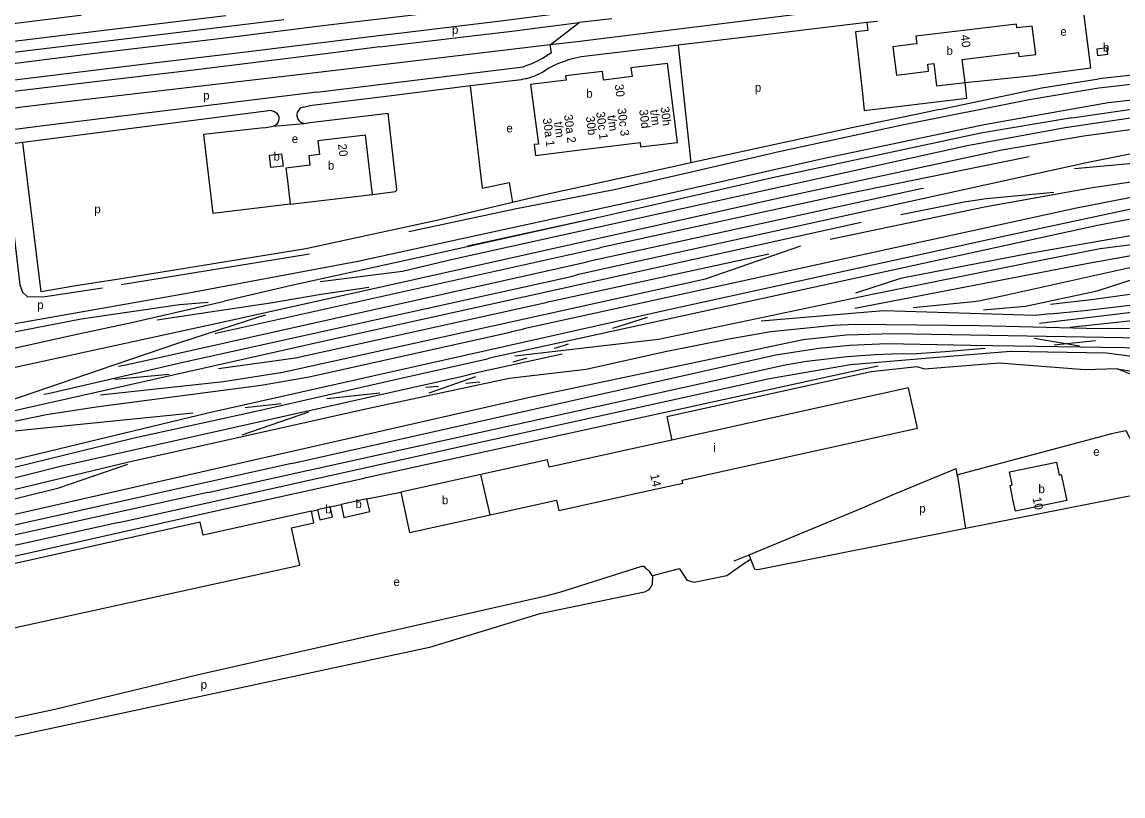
# Model space of a CAD drawing. Extents: x 161494 to 163033, y 383688 to 384862.
# Drawn here: x 162005 to 162517, y 383712 to 384073 of the extents above; entities that cross this region are included whole.
import ezdxf

# ---------------------------------------------------------------- set-up
doc = ezdxf.new("R2010")
doc.units = 0
for name, color, linetype in [('BLT_Basislijn', 7, 'Continuous'), ('BLT_Bebouwing', 7, 'Continuous'), ('BLT_Centroide', 7, 'Continuous'), ('BLT_Huisnummer', 7, 'Continuous'), ('BLT_Huisnummer_reeks', 7, 'Continuous'), ('BLT_Onderverdeling_panden', 7, 'Continuous'), ('BLT_Spoorlijn', 7, 'Continuous'), ('BLT_Vlakafsluiter', 7, 'Continuous')]:
    doc.layers.add(name, color=color, linetype=linetype)

msp = doc.modelspace()

# ---------------------------------------------------------------- linework, layer by layer
at = {"layer": 'BLT_Basislijn'}
for p, q in [((162126.86, 384073.58), (162015.41, 384059.99)), ((162099.94, 384075.38), (162038.28, 384067.96)), ((162402.95, 384072.84), (162397.98, 384072.25)), ((162397.98, 384072.25), (162398.41, 384068.65)), ((162038.28, 384067.96), (162016.53, 384065.35)), ((162016.53, 384065.35), (161970.53, 384059.79)), ((162250.72, 384061.85), (162144.18, 384049.27)), ((162263.36, 384063.34), (162250.72, 384061.85)), ((162251.31, 384058.43), (162250.72, 384061.85)), ((162310.31, 384061.73), (162304.32, 384061.01)), ((162310.31, 384061.73), (162316.22, 384006.99)), ((162015.41, 384059.99), (161924.88, 384049.24)), ((162304.32, 384061.01), (162265.1, 384056.31)), ((162142.18, 384039.89), (162238.14, 384051.73)), ((162144.18, 384049.27), (162016.75, 384034.31)), ((162443.66, 384044.4), (162473.95, 384047.55)), ((162551.62, 384051.16), (162505.86, 384046.13)), ((162213.64, 384042.77), (162174.52, 384037.93)), ((162237.25, 384045.7), (162213.64, 384042.77)), ((162219.25, 383995.24), (162213.64, 384042.77)), ((162142.18, 384039.89), (162017.64, 384024.49)), ((162174.52, 384037.93), (162138.87, 384033.51)), ((162016.75, 384034.31), (161960.62, 384027.39)), ((162120.98, 384031.33), (162088.58, 384027.16)), ((162135.87, 384032.98), (162138.87, 384033.51)), ((162088.58, 384027.16), (162005.59, 384016.47)), ((162136.37, 384025.38), (162138.97, 384025.83)), ((162138.97, 384025.83), (162141.65, 384026.15)), ((162141.65, 384026.15), (162175.35, 384030.07)), ((162117.62, 384023.23), (162089.48, 384020.18)), ((162117.62, 384023.23), (162122.09, 384024.04)), ((162122.09, 384024.04), (162136.37, 384025.38)), ((162005.59, 384016.47), (161998.45, 384015.55)), ((162089.48, 384020.18), (162093.89, 383983.46)), ((162311.36, 384005.93), (162246.2, 383991.7)), ((162316.22, 384006.99), (162311.36, 384005.93)), ((162246.2, 383991.7), (162233.2, 383988.6)), ((162129.89, 383987.73), (162093.89, 383983.46)), ((162051.28, 383950.46), (162138.8, 383964.68)), ((162411.05, 383853), (162439.57, 383864.71)), ((162440.16, 383861.18), (162439.57, 383864.71)), ((162165.51, 383850.67), (162181.24, 383853.7)), ((162148.51, 383846.88), (162153.51, 383847.98)), ((162139.81, 383844.85), (162142.61, 383845.56)), ((162344.15, 383822.1), (162343.24, 383824.58))]:
    msp.add_line(p, q, dxfattribs=at)
for points in [[(162037.04, 384088.82), (162036.53, 384080.07), (162035.9, 384078.31), (162034.83, 384076.99), (162033.62, 384076.14), (162032.14, 384075.62), (161973.45, 384068.36), (161971.82, 384068.3), (161970.32, 384068.57), (161968.94, 384069.14), (161967.71, 384069.97), (161966.53, 384071.23), (161965.71, 384072.68), (161965.29, 384073.99), (161965.13, 384075.37), (161965.09, 384077.77), (161965.12, 384080.52)], [(162474.93, 384090.36), (162374.06, 384077.18), (162263.36, 384063.34)], [(162473.95, 384047.55), (162502.09, 384051.2), (162498.03, 384084.42)], [(162212.3, 384078.63), (162147.57, 384071.14), (162099.53, 384065.02), (162042.92, 384058.28)], [(162257.94, 384076.77), (162229.07, 384073.11), (162180.34, 384067.19), (162170.91, 384066.06)], [(162171.47, 384060.99), (162213.02, 384065.92), (162231.75, 384068.17), (162264.28, 384072.26)], [(162279.49, 384074.03), (162264.28, 384072.26)], [(162397.98, 384072.25), (162341.73, 384065.49), (162310.31, 384061.73)], [(162398.41, 384068.65), (162392.66, 384067.99), (162395.96, 384039.21), (162396.82, 384031.44), (162444.53, 384037.15), (162443.66, 384044.4)], [(162170.91, 384066.06), (162109.23, 384058.59), (162065, 384053.23)], [(162042.92, 384058.28), (161985.85, 384051.24), (161928.63, 384044.5)], [(162171.47, 384060.99), (162144.99, 384057.6), (162116.12, 384053.94), (162085, 384050.13), (162065.15, 384047.88)], [(162238.14, 384051.73), (162240.01, 384052.39), (162241.85, 384053.12), (162243.66, 384053.93), (162245.43, 384054.81), (162247.17, 384055.76), (162248.86, 384056.78), (162250.52, 384057.87), (162251.31, 384058.43)], [(162065, 384053.23), (161972.34, 384041.96), (161944.6, 384038.44)], [(162184.97, 383975.01), (162234.27, 383985.59), (162280.45, 383994.61), (162317.07, 384003.01), (162357.89, 384012.37), (162415.17, 384024.78), (162473.52, 384036.49), (162505.94, 384041.95), (162556.37, 384047.61), (162586.74, 384050.32), (162625.03, 384052.18), (162657.62, 384052.19), (162690.5, 384051.66)], [(162265.1, 384056.31), (162263.12, 384055.91), (162261.15, 384055.43), (162259.2, 384054.87), (162257.28, 384054.23), (162255.38, 384053.52), (162253.51, 384052.73), (162251.68, 384051.88), (162249.79, 384050.9)], [(162065.15, 384047.88), (162001.35, 384040.13), (161948.68, 384033.93)], [(162239.64, 384046.15), (162239.17, 384046.04), (162237.72, 384045.77), (162237.25, 384045.7)], [(162249.79, 384050.9), (162248.6, 384050.04), (162247.35, 384049.26), (162246.07, 384048.54), (162244.75, 384047.89), (162243.39, 384047.31), (162242.01, 384046.81), (162240.6, 384046.39), (162239.64, 384046.15)], [(162431.72, 384031.85), (162479.43, 384041.97), (162505.86, 384046.13)], [(162956.78, 384021.72), (162940.81, 384022.86), (162844.13, 384032.25), (162776, 384038.39), (162705.31, 384043.59), (162655, 384044.9), (162627.45, 384044.8), (162579.26, 384042.49), (162510.26, 384034.87), (162452.51, 384024.7), (162377.46, 384008.85), (162301.58, 383991.65), (162233.15, 383976.81), (162161.35, 383961.08), (162082.65, 383946.35), (162000.1, 383931.74), (161945.86, 383921.22), (161938.95, 383921.37)], [(162120.98, 384031.33), (162121.52, 384031.27), (162122.06, 384031.12), (162122.56, 384030.91), (162123.02, 384030.62), (162123.44, 384030.26), (162123.81, 384029.85), (162124.11, 384029.4), (162124.34, 384028.9), (162124.49, 384028.37), (162124.57, 384027.83), (162124.57, 384027.28), (162124.48, 384026.74), (162124.32, 384026.22), (162124.09, 384025.72), (162123.78, 384025.27), (162123.42, 384024.86), (162122.99, 384024.51), (162122.52, 384024.23), (162122.09, 384024.04)], [(162135.87, 384032.98), (162135.34, 384032.8), (162134.84, 384032.55), (162134.39, 384032.23), (162133.98, 384031.85), (162133.64, 384031.42), (162133.35, 384030.93), (162133.15, 384030.42), (162133.01, 384029.88), (162132.96, 384029.32), (162132.99, 384028.77), (162133.09, 384028.22), (162133.27, 384027.7), (162133.53, 384027.2), (162133.85, 384026.75), (162134.24, 384026.35), (162134.68, 384026.01), (162135.16, 384025.73), (162135.68, 384025.53), (162136.22, 384025.4), (162136.37, 384025.38)], [(162431.72, 384031.85), (162423.85, 384030.18), (162391.05, 384023.32), (162316.22, 384006.99)], [(162168.17, 383992.34), (162178.74, 383993.7), (162179.33, 383994.07), (162179.41, 383994.62), (162175.35, 384030.07)], [(162017.64, 384024.49), (161979.82, 384019.8), (161964.19, 384023.37)], [(162233.2, 383988.6), (162198.65, 383980.36), (162137.19, 383967.01), (162051.32, 383953.01), (162029.31, 383949.67), (162013.98, 383947), (162005.59, 384016.47)], [(161997.08, 384010.02), (162004.14, 383950.22), (162005.39, 383946.88), (162007.62, 383944.64), (162015.93, 383944.83), (162042.51, 383948.79)], [(162219.25, 383995.24), (162231.67, 383997.8), (162233.2, 383988.6)], [(162514.37, 383911.16), (162573.7, 383901.56), (162613.61, 383900.68), (162655.85, 383904.66), (162788.99, 383916.53), (162852.19, 383929.33), (162857.95, 383930.73)], [(162459.47, 383913.71), (162424.85, 383911.06), (162421.45, 383912.07), (162400.03, 383909.78), (162304.94, 383888.77), (162307.31, 383878.02)], [(162514.37, 383911.16), (162499.43, 383910.67), (162459.47, 383913.71)], [(162524.19, 383906.26), (162521.33, 383908.32), (162514.37, 383911.16)], [(162524.4, 383869.94), (162523.12, 383873.79), (162518.74, 383881.94), (162518.35, 383882.35), (162511.81, 383880.82), (162440.37, 383861.85), (162440.16, 383861.18)], [(162440.16, 383861.18), (162443.86, 383836.78)], [(162527.6, 383858.28), (162527.82, 383857.32), (162527.69, 383855.14), (162526.15, 383853.19), (162524.72, 383852.77), (162443.86, 383836.78)], [(162343.24, 383824.58), (162395.99, 383846.52), (162411.05, 383853)], [(162443.86, 383836.78), (162347.36, 383817.56), (162345.99, 383817.74), (162344.15, 383822.1)], [(162344.15, 383822.1), (162343.67, 383822.22), (162340.77, 383820.4), (162332.94, 383814.78), (162317.73, 383811.68), (162314.64, 383812.66), (162311.04, 383818.01), (162310.18, 383817.93), (162298.39, 383814.86)], [(162336.35, 383821.72), (162343.24, 383824.58)], [(161857.05, 383717.49), (161900, 383726.97), (162020.37, 383752.79), (162087.25, 383768.84), (162248.7, 383805.52), (162255.21, 383807.22), (162293.41, 383819.32), (162294.37, 383819.23), (162295.04, 383818.42), (162296.07, 383817.77)], [(162298.39, 383814.86), (162297.95, 383815.15), (162297.13, 383816.68), (162296.07, 383817.77)], [(162298.39, 383814.86), (162298.2, 383810.83), (162297.43, 383809.38), (162296.37, 383808.09), (162294.68, 383807.19), (162245.95, 383797.11), (162194.64, 383781.44), (161900, 383718.26), (161896.94, 383717.62), (161877.03, 383714.47), (161850.45, 383712.34)]]:
    msp.add_lwpolyline(points, dxfattribs=at)
at = {"layer": 'BLT_Bebouwing'}
for p, q in [((162467.57, 384071.6), (162425.99, 384066.57)), ((162425.99, 384066.57), (162420.75, 384065.93)), ((162476.27, 384057.43), (162476.52, 384057.46)), ((162309.88, 384016.49), (162305.31, 384053.28)), ((162129.89, 383987.73), (162168.17, 383992.34)), ((162362.65, 383890.25), (162307.31, 383878.02)), ((162307.31, 383878.02), (162288.81, 383873.93)), ((162288.81, 383873.93), (162250.29, 383865.43)), ((162218.56, 383861.94), (162181.24, 383853.7)), ((162222.78, 383843.26), (162253.68, 383850.09))]:
    msp.add_line(p, q, dxfattribs=at)
for points in [[(162474.92, 384070.68), (162467.78, 384069.81), (162467.57, 384071.6)], [(162476.52, 384057.46), (162474.92, 384070.68)], [(162419.66, 384062.17), (162410.12, 384061.01), (162411.72, 384047.8), (162426.73, 384049.61), (162426.33, 384052.96), (162429.18, 384053.3), (162430.46, 384042.8)], [(162420.75, 384065.93), (162421.18, 384062.35), (162419.66, 384062.17)], [(162430.46, 384042.8), (162443.66, 384044.4), (162442.36, 384055.14), (162468.46, 384058.3), (162468.68, 384056.51), (162472.78, 384057.01)], [(162472.78, 384057.01), (162476.52, 384057.46)], [(162305.31, 384053.28), (162288.3, 384051.19), (162288.8, 384047.12), (162275.51, 384045.49), (162275.01, 384049.56), (162257.93, 384047.45), (162258.16, 384045.55), (162241.64, 384043.39), (162245.26, 384015.73), (162243.3, 384015.48), (162243.91, 384010.46), (162262.15, 384012.81), (162292.53, 384016.51), (162292.78, 384014.41), (162309.88, 384016.49)], [(162142.71, 384017.26), (162143.47, 384010.93), (162138.45, 384010.33), (162138.98, 384005.87), (162127.85, 384004.53), (162128.4, 384000), (162129.89, 383987.73)], [(162168.17, 383992.34), (162167.25, 384000), (162164.84, 384019.93), (162142.71, 384017.26)], [(162120.2, 384010.53), (162125.88, 384011.21), (162126.56, 384005.53), (162120.89, 384004.85), (162120.2, 384010.53)], [(162366.8, 383871.47), (162421.56, 383883.57), (162417.41, 383902.34), (162362.65, 383890.25)], [(162250.29, 383865.43), (162249.55, 383868.79), (162218.56, 383861.94)], [(162293.27, 383853.7), (162312.37, 383857.91), (162312.05, 383859.38), (162366.8, 383871.47)], [(162181.24, 383853.7), (162185.38, 383835), (162222.78, 383843.26)], [(162253.68, 383850.09), (162254.76, 383845.19), (162293.27, 383853.7)], [(162142.61, 383845.56), (162143.66, 383840.86), (162149.56, 383842.19), (162148.51, 383846.88)], [(162148.51, 383846.88), (162142.61, 383845.56)], [(162153.51, 383847.98), (162154.85, 383841.99), (162166.85, 383844.68), (162165.51, 383850.67)], [(162165.51, 383850.67), (162153.51, 383847.98)], [(162000, 383790.34), (162134.33, 383819.8), (162130.48, 383837.21), (162140.9, 383839.53), (162139.81, 383844.85)], [(162139.81, 383844.85), (162089.38, 383833.76), (162088.04, 383839.79), (162000, 383820.13)]]:
    msp.add_lwpolyline(points, dxfattribs=at)
for points in [[(162504.98, 384059.97), (162505.29, 384057.02), (162510.02, 384057.57), (162509.69, 384060.51)], [(162490.96, 383849.84), (162467.12, 383844.83), (162466.11, 383849.64), (162464.61, 383856.9), (162465.6, 383857.11), (162464.33, 383863.19), (162486.15, 383867.78), (162487.44, 383861.7), (162488.43, 383861.91)]]:
    msp.add_lwpolyline(points, close=True, dxfattribs=at)
at = {"layer": 'BLT_Onderverdeling_panden'}
msp.add_line((162222.78, 383843.26), (162218.56, 383861.94), dxfattribs=at)
at = {"layer": 'BLT_Spoorlijn'}
for p, q in [((162483.18, 383936.8), (162476.31, 383935.97)), ((162508.37, 383935.84), (162478.25, 383932.3)), ((162529.41, 383934.28), (162492.32, 383930.4)), ((162475.74, 383925.46), (162496.84, 383921.86)), ((162485.12, 383922.28), (162504.3, 383924.29)), ((162073.54, 383908.58), (162048.26, 383906.16)), ((162192.96, 383902.62), (162198.77, 383903.13)), ((162194.47, 383899.99), (162216.19, 383907.59)), ((162146.86, 383897.28), (162171.6, 383900.03)), ((162108.95, 383893.19), (162125.62, 383895.06)), ((162138.29, 383890.98), (162107.29, 383880.28))]:
    msp.add_line(p, q, dxfattribs=at)
for points in [[(162851.52, 384017.92), (162815.39, 384024.3), (162780.35, 384028.34), (162734.32, 384032.49), (162682.28, 384035.6), (162657.55, 384036.07), (162644.62, 384036.06), (162620.91, 384035.6), (162600, 384034.57), (162572.62, 384033.21), (162544.84, 384030.9), (162520.54, 384027.83), (162490.18, 384023.26), (162444.69, 384014.9), (162206.08, 383962.22), (162182.09, 383956.51), (162143.86, 383951.57)], [(162493.36, 384027.95), (162525.34, 384032.6), (162559.19, 384036.38), (162587.86, 384038.71), (162602.55, 384039.57), (162618.77, 384040.28), (162643.1, 384040.8), (162670.1, 384040.71)], [(162900.86, 384011.36), (162871.5, 384014.34), (162849.2, 384016.61), (162786.11, 384023.02), (162743.32, 384027.37), (162714.49, 384029.62), (162675.59, 384031.05), (162617.43, 384030.81), (162571.29, 384028.11), (162530.64, 384023.81), (162498.89, 384019.36), (162460.78, 384012.83), (162360.78, 383991.35), (162187.34, 383952.61), (162103.09, 383933.78), (162003.41, 383912.03), (161897.47, 383888.44), (161858.44, 383879.75), (161796.71, 383866.01)], [(162015.34, 383899.38), (162017.25, 383899.68), (162080.65, 383914.34), (162260.47, 383954.06), (162264.14, 383955.18), (162275.03, 383957.62), (162500.2, 384007.1), (162541.18, 384015.46), (162562.76, 384019.37), (162588.28, 384023.03), (162600, 384024.15), (162615.59, 384025.65), (162626.19, 384026.21), (162676.14, 384026.61), (162705.93, 384025.41), (162732.39, 384023.5), (162757.2, 384021.52), (162782.07, 384018.89)], [(162493.36, 384027.95), (162450.96, 384020.86), (162354.12, 384000)], [(162718.29, 384020.75), (162713.88, 384020.92), (162695.07, 384020.96), (162676.79, 384020.24), (162656.02, 384019.05), (162600, 384013.9), (162494.64, 384004.23)], [(162941.48, 383999.68), (162885.08, 384004.73), (162828.99, 384008.31), (162785.99, 384009.38), (162740.84, 384009.38), (162711.24, 384008.27), (162666.85, 384005.72), (162629.14, 384002.14), (162592.38, 383997.29), (162554.12, 383991.4), (162521.58, 383985.67), (162460.79, 383972.63), (162306.5, 383938.7), (162091.55, 383890.56), (161917.85, 383848.6), (161738.59, 383808.47)], [(162095.01, 383927.45), (162095.33, 383927.68), (162273.9, 383967.38), (162274.44, 383967.78), (162386.85, 383992.3), (162388.93, 383992.71), (162450.6, 384005.36), (162473.49, 384009.96)], [(162611.49, 384009.61), (162600, 384008.23), (162554.37, 384002.74), (162541.63, 384001.06), (162502.06, 383995.25), (162452.78, 383986.34), (162381.01, 383971.32)], [(162905.58, 383999.21), (162868.86, 384001.46), (162849.7, 384002.66), (162790.91, 384004.97), (162738.08, 384005.04), (162706.63, 384003.77), (162665.91, 384000.87), (162614.64, 383996.13), (162600, 383994.1), (162581.38, 383991.52), (162547.62, 383985.93), (162505.3, 383977.83), (162222.56, 383916.14), (162220.88, 383915.5), (162180.02, 383906.4), (162114.68, 383891.49), (162057.27, 383878.89), (162001, 383865.09), (161973.74, 383858.18), (161900, 383840.1), (161740.55, 383804.02)], [(161730.85, 383826.01), (161894.71, 383863.07), (161900, 383864.57), (161902.38, 383864.96), (161983.42, 383883.13), (162016.6, 383889.91), (162039.67, 383893.48), (162116.35, 383903.49), (162138.72, 383907.4), (162232.76, 383928.3), (162232.82, 383928.45), (162238.5, 383929.73), (162238.57, 383929.89), (162495.51, 383986.06), (162549.61, 383996.68)], [(162050.01, 383912.39), (162052.66, 383912.83), (162073.16, 383917.38), (162267.95, 383960.93), (162268.01, 383961.09), (162423.18, 383995.14), (162424.3, 383995.25)], [(162354.12, 384000), (162272.82, 383981.43)], [(162907.68, 383994.11), (162844.71, 383995.65), (162793.91, 383994.99), (162738.55, 383993.66), (162714.69, 383992.18), (162687.37, 383990.08), (162600, 383981.71), (162536.18, 383975.6), (162528.51, 383974.48), (162472.93, 383964.7), (162413.7, 383953.16), (162392.67, 383946.32)], [(162413.77, 383982.9), (162443.28, 383988.79), (162453.46, 383990.34), (162484.93, 383993.36)], [(162452.21, 383938.56), (162471.82, 383940.35), (162505.05, 383947.43), (162546.3, 383960.72), (162600, 383972.91), (162658.88, 383985.79)], [(162272.82, 383981.43), (162190.66, 383963.17), (162130.51, 383949.89)], [(162272.82, 383981.43), (162212.27, 383968.16)], [(162395.33, 383979.18), (162144.35, 383923.63), (161977.36, 383886.22), (161907.71, 383872.27), (161900, 383871.29), (161780.14, 383857.4), (161723.5, 383844.79)], [(162234.3, 383917.16), (162301.05, 383924.91), (162401.28, 383946), (162480.43, 383961.98), (162506.53, 383967.15), (162525.98, 383969.57), (162555.06, 383972.87), (162619.14, 383978.6)], [(162937.09, 383979.39), (162885.92, 383963.59), (162838.53, 383952.88), (162810.99, 383946.65), (162798.67, 383945.04), (162734.95, 383938.99), (162640.6, 383930.03), (162616.88, 383927.78), (162559, 383928.82), (162530.82, 383929.76), (162500.1, 383929.97)], [(162392.46, 383939.3), (162500.09, 383960.2), (162519.93, 383963.73), (162538.91, 383966.11), (162578.77, 383969.81)], [(162041.67, 383899.09), (162098.83, 383905.26), (162126.37, 383909.55), (162323.01, 383953.08), (162367.37, 383968.42)], [(162096.48, 383911.28), (162132.24, 383916.25), (162249.49, 383942.13), (162249.55, 383942.29), (162251.13, 383942.64), (162352.39, 383964.66)], [(162419.59, 383939.61), (162447.63, 383942.41), (162450.08, 383942.82), (162463.07, 383945.51), (162524.5, 383959.22)], [(162483.42, 383941.17), (162502.43, 383943.42), (162520.33, 383945.85), (162522.52, 383946.03), (162557.82, 383951.09), (162600, 383954.91), (162606.92, 383955.53)], [(162068.05, 383933.95), (162095.81, 383938.09), (162120.73, 383941.8), (162144.3, 383945.84), (162166.42, 383949.19)], [(162130.51, 383949.89), (162099.3, 383942.63)], [(162483.18, 383936.8), (162499.25, 383938.35), (162550.66, 383944.41), (162600, 383948.85), (162607.49, 383949.53)], [(161717.09, 383867.34), (161891.12, 383897), (161932.12, 383905.15), (161966.91, 383913.19), (162031.41, 383927.43), (162056.89, 383932.93), (162099.3, 383942.63)], [(162091.72, 383942.03), (162078.35, 383940.97), (162032.72, 383934.33)], [(162685.4, 383942.61), (162638.15, 383937.9), (162627.72, 383936.86), (162596.57, 383936.35), (162554.47, 383937.41), (162527.37, 383938.1), (162508.37, 383935.84)], [(161973.61, 383887.7), (161975.27, 383888.11), (162047.51, 383912.9), (162078.57, 383923.36), (162115.77, 383935.53), (162118.45, 383936.24)], [(162032.72, 383934.33), (161999.97, 383927.9)], [(162279.85, 383930.06), (162296.05, 383935.21)], [(162476.31, 383935.97), (162405.74, 383938.2), (162348.83, 383933.3)], [(162423.37, 383915.96), (162442.18, 383917.5), (162464.81, 383919.36), (162481.96, 383919.04), (162509.3, 383918.54), (162531.03, 383915.8), (162561.33, 383911.2), (162576.79, 383910.32), (162609.28, 383908.25), (162632.92, 383907.84), (162656.75, 383909.89), (162799.49, 383923.96), (162812.19, 383926.35), (162852.54, 383935.02)], [(162500.1, 383929.97), (162450.25, 383931.18), (162392.65, 383931.81), (162382.47, 383931.26), (162353.39, 383928.39), (162334.69, 383925.09), (162304.14, 383919.1), (162267.53, 383910.9), (162231.75, 383906.69), (162166.47, 383892.65)], [(162584.74, 383924.89), (162561.28, 383924.73), (162410.59, 383927.36), (162388.32, 383926.8), (162368.34, 383924.63), (162241.85, 383897.88), (162061.12, 383856.79)], [(162091.56, 383853.64), (162360.09, 383912.97), (162369.87, 383914.65), (162388.83, 383916.92), (162401.93, 383917.87), (162409.4, 383918.11), (162421.07, 383918.2)], [(162130.47, 383867.03), (162355.7, 383917.69), (162375.71, 383920.79), (162390.03, 383922.19), (162407.33, 383922.9), (162446.26, 383922.2), (162538.25, 383920.77)], [(162252.57, 383920.77), (162253.49, 383920.89), (162259.21, 383922.76)], [(162421.07, 383918.2), (162434.41, 383919.26), (162453.05, 383920.75)], [(162256.39, 383917.91), (162217.24, 383909.43), (162209.3, 383907.49), (162022.98, 383865.7), (161954.74, 383848.51), (161900, 383835.54), (161866.29, 383827.45), (161742.42, 383799.74)], [(162050.18, 383839.64), (162207.72, 383874.76), (162352.68, 383906.66), (162390.4, 383913.21), (162423.37, 383915.96)], [(162233.47, 383914.4), (162240.03, 383916.28)], [(161754.32, 383769.07), (161900, 383801.22), (162098.04, 383845.62), (162164.2, 383860.2), (162165.2, 383860.57), (162396.44, 383911.1), (162403.33, 383912.46)], [(162211.51, 383904.47), (162218.1, 383905.04)], [(162166.47, 383892.65), (162054.27, 383867.61), (161900, 383830.52), (161864.25, 383822.27), (161744.09, 383795.55)], [(162084.52, 383890.44), (161970.83, 383879.04)], [(162130.47, 383867.03), (161900, 383815.76), (161885.6, 383812.15), (161749.42, 383782.25)], [(162054.25, 383866.57), (162021.59, 383855.48), (161912.53, 383828.39), (161900, 383825.65), (161877.44, 383820.08), (161745.83, 383791.21)], [(162061.12, 383856.79), (161900, 383820.16), (161877.93, 383814.9), (161747.79, 383786.3)], [(162091.56, 383853.64), (161899.96, 383811.43), (161751, 383778.31)], [(162050.18, 383839.64), (161899.96, 383806.47), (161752.71, 383774.04)]]:
    msp.add_lwpolyline(points, dxfattribs=at)
at = {"layer": 'BLT_Vlakafsluiter'}
msp.add_line((162250.72, 384061.85), (162264.28, 384072.26), dxfattribs=at)

# ---------------------------------------------------------------- texts
at = {"layer": 'BLT_Centroide'}
for s, p in [('p', (162205.09, 384066.99)), ('e', (162487.97, 384066.15)), ('b', (162507.77, 384058.8)), ('b', (162435, 384057.22)), ('b', (162267.53, 384037.33)), ('p', (162345.95, 384040.14)), ('p', (162089.37, 384036.43)), ('e', (162230.38, 384021.17)), ('e', (162130.56, 384016.23)), ('b', (162122.05, 384008.03)), ('b', (162147.37, 384003.81)), ('p', (162038.77, 383983.54)), ('p', (162012.2, 383938.97)), ('i', (162326.62, 383872.44)), ('e', (162503.28, 383870.68)), ('b', (162477.77, 383853.28)), ('b', (162200.38, 383848.12)), ('b', (162146.08, 383843.88)), ('b', (162160.18, 383846.34)), ('p', (162422.38, 383844.22)), ('e', (162177.89, 383810.05)), ('p', (162088.23, 383762.21))]:
    msp.add_text(s, height=4, dxfattribs=at).set_placement(p)
at = {"layer": 'BLT_Huisnummer'}
for s, rotation, p in [('40', 276.9039, (162441.63, 384066.44)), ('20', 276.8774, (162152.04, 384015.65)), ('14', 282.455, (162297.24, 383861.75)), ('10', 281.885, (162475.06, 383851))]:
    msp.add_text(s, height=4, rotation=rotation, dxfattribs=at).set_placement(p)
at = {"layer": 'BLT_Huisnummer_reeks'}
for s, p in [('30', (162280.76, 384043.37)), ('30c 3', (162281.97, 384032.24)), ('30d', (162292.13, 384031.65)), ('t/m', (162297.19, 384031.54)), ('30h', (162302.06, 384032.85)), ('30a 1', (162247.28, 384027.59)), ('t/m', (162252.54, 384025.89)), ('30a 2', (162257.15, 384029.26)), ('30b', (162267.33, 384028.49)), ('30c 1', (162272.11, 384030.57)), ('t/m', (162277.36, 384028.94))]:
    msp.add_text(s, height=4, rotation=277.3114, dxfattribs=at).set_placement(p)

doc.saveas('drawing.dxf')
